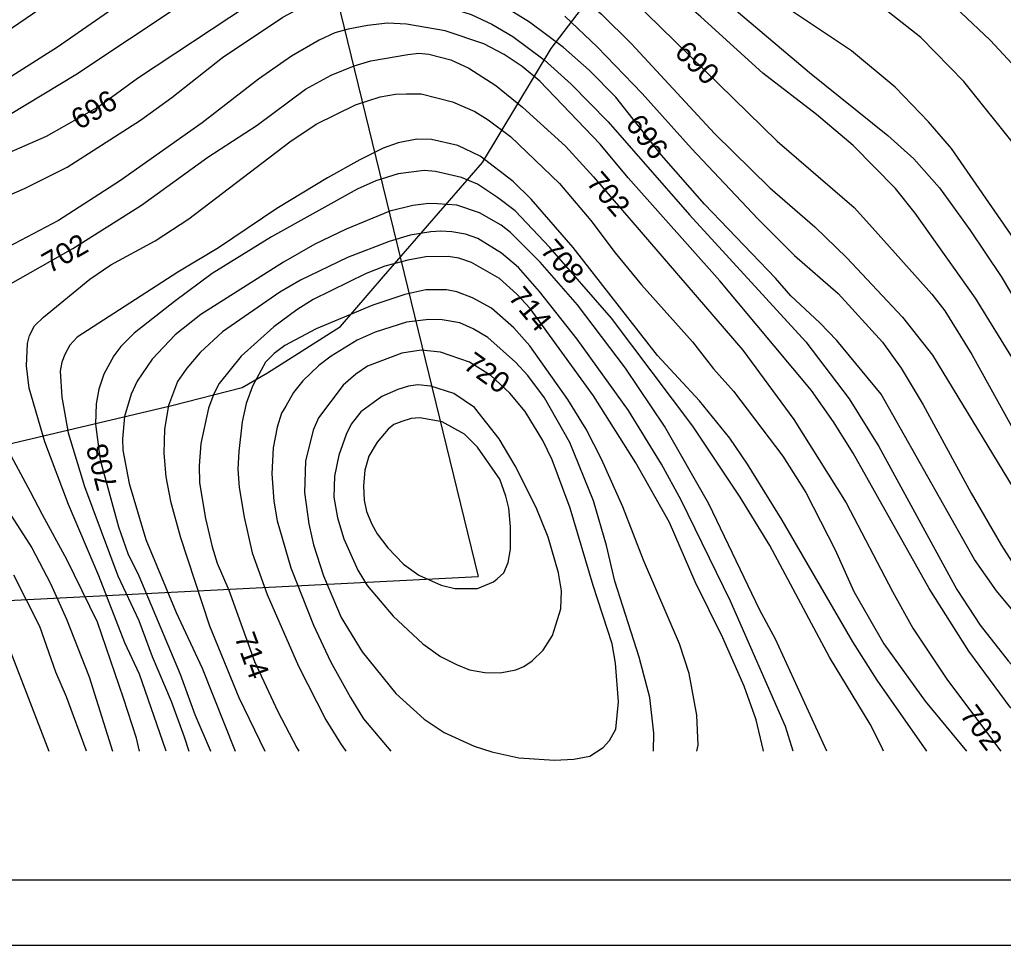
# Model space of a CAD drawing. Extents: x -709418 to -703832, y -1161719 to -1157826.
# Drawn here: x -706447 to -706070.4, y -1161718.9 to -1161364.7 of the extents above; entities that cross this region are included whole.
import ezdxf

# ---------------------------------------------------------------- set-up
doc = ezdxf.new("R2010")
doc.units = 0
for name, color, linetype in [('103_hranice KÚ', 7, 'Continuous'), ('120_vrstevnice hlavní', 7, 'Continuous'), ('121_vrstevnice hlavní_popis', 7, 'Continuous'), ('122_vrstevnice základní', 7, 'Continuous'), ('723_radioreléová trasa_UAP', 7, 'Continuous'), ('800_mřížka', 7, 'Continuous')]:
    doc.layers.add(name, color=color, linetype=linetype)

msp = doc.modelspace()

# ---------------------------------------------------------------- linework, layer by layer
at = {"layer": '103_hranice KÚ'}
msp.add_lwpolyline([(-706454.11, -1161527.78), (-706388.65, -1161512.35), (-706361.81, -1161505.4), (-706352.07, -1161499.85), (-706324.15, -1161482.08), (-706307.71, -1161462.97), (-706269.8, -1161419.34), (-706243.48, -1161375.76), (-706215.3, -1161338.76), (-706167.43, -1161298.96), (-706131.19, -1161259.29), (-706118.24, -1161260.88), (-706121.87, -1161224.74), (-706132.26, -1161199.29), (-706140.22, -1161183.53), (-706150.49, -1161170.73), (-706153.76, -1161155.91), (-706152.5, -1161152.34), (-706147.72, -1161124.93)], dxfattribs=at)
at = {"layer": '120_vrstevnice hlavní'}
for points in [[(-706303.48, -1161253.38), (-706295.5, -1161254.38), (-706277.14, -1161258.04), (-706268.43, -1161260.36), (-706252.47, -1161266.06), (-706224.54, -1161279.46), (-706184.64, -1161300.55), (-706144.74, -1161319.35), (-706124.8, -1161330.47), (-706104.42, -1161345.15), (-706075.35, -1161372.51), (-706050.41, -1161399.44)], [(-706455.1, -1161371.22), (-706431.59, -1161355.12), (-706410.5, -1161341.87), (-706388.7, -1161329.04), (-706369.6, -1161319.64), (-706346.8, -1161312.23), (-706324, -1161308.81), (-706314.88, -1161308.53), (-706302.34, -1161309.24), (-706286.39, -1161312.09), (-706266.44, -1161319.07), (-706254.47, -1161324.91), (-706246.49, -1161329.76), (-706234.52, -1161338.31), (-706212.72, -1161356.55), (-706157, -1161411.12), (-706127.5, -1161436.49), (-706120.5, -1161444.3), (-706097.72, -1161469.69), (-706092.73, -1161476.1), (-706082.47, -1161492.77), (-706061.81, -1161529.96)], [(-706224.71, -1161412.26), (-706247.77, -1161388.18), (-706254.61, -1161382.62), (-706261.45, -1161378.06), (-706269.29, -1161373.93), (-706284.1, -1161368.94), (-706298.92, -1161366.38), (-706306.11, -1161366.06), (-706313.74, -1161366.95), (-706321.15, -1161368.37), (-706326.33, -1161369.76), (-706332.27, -1161372.51), (-706342.95, -1161378.63), (-706355.49, -1161387.47), (-706377.15, -1161404.14), (-706408.79, -1161426.51), (-706432.16, -1161441.47), (-706453.96, -1161453.01)], [(-706052.39, -1161644.59), (-706054.26, -1161642.67), (-706067.8, -1161627.71), (-706083.61, -1161606.34), (-706098.72, -1161582.4), (-706127.79, -1161530.53), (-706135.34, -1161518.56), (-706143.75, -1161506.59), (-706178.94, -1161464.56), (-706214, -1161425.23), (-706224.71, -1161412.26)], [(-706137.94, -1161644.59), (-706157.57, -1161601.78), (-706163.56, -1161590.66), (-706183.08, -1161549.91), (-706200.03, -1161520.27), (-706214.99, -1161498.04), (-706233.38, -1161473.82), (-706247.63, -1161457.43), (-706259.03, -1161446.18), (-706262.59, -1161443.32), (-706270.85, -1161438.62), (-706279.55, -1161435.63), (-706286.96, -1161435.2), (-706290.34, -1161434.96), (-706296.45, -1161435.75), (-706305.22, -1161437.93), (-706322.01, -1161444.89), (-706333.98, -1161450.59), (-706345.95, -1161457.43), (-706377.58, -1161477.52), (-706387.41, -1161485.22), (-706396.25, -1161494.62), (-706401.95, -1161503.03), (-706404.23, -1161508.02), (-706406.79, -1161516.57), (-706407.65, -1161525.12), (-706407.51, -1161529.39), (-706405.08, -1161542.22)], [(-706293.22, -1161491.2), (-706300.63, -1161492.34), (-706313.73, -1161497.31), (-706318.3, -1161500.32), (-706323.15, -1161504.6), (-706332.55, -1161516.99), (-706334.55, -1161521.7), (-706337.54, -1161533.67), (-706337.97, -1161545.64), (-706336.26, -1161557.6), (-706334.41, -1161565.58), (-706330.7, -1161577.55), (-706323.86, -1161593.51), (-706315.88, -1161606.62), (-706302.91, -1161622.58), (-706292.08, -1161632.41), (-706284.39, -1161637.4), (-706272.99, -1161642.67), (-706266.15, -1161644.81), (-706255.89, -1161647.09), (-706242.21, -1161648.09), (-706234.8, -1161647.66), (-706228.67, -1161646.52), (-706223.54, -1161643.24), (-706221.12, -1161640.54), (-706218.7, -1161636.12), (-706217.7, -1161625.72), (-706218.84, -1161610.9), (-706220.12, -1161603.49), (-706227.39, -1161581.26), (-706236.23, -1161551.62), (-706243.07, -1161533.1), (-706246.63, -1161525.69), (-706253.47, -1161514.57), (-706259.31, -1161507.59), (-706266.58, -1161500.89), (-706274.7, -1161495.76), (-706285.82, -1161491.92), (-706293.22, -1161491.2)], [(-706457.09, -1161543.93), (-706442.27, -1161566.73), (-706435.15, -1161580.4), (-706429.02, -1161594.08), (-706420.41, -1161616.2), (-706411.36, -1161644.59)], [(-706405.08, -1161542.22), (-706398.67, -1161563.59), (-706386.99, -1161591.52), (-706377.15, -1161612.89), (-706364.47, -1161644.59)]]:
    msp.add_lwpolyline(points, dxfattribs=at)
at = {"layer": '122_vrstevnice základní'}
for points in [[(-706065.38, -1161413.4), (-706085.47, -1161388.32), (-706102, -1161371.51), (-706117.96, -1161358.82), (-706131.92, -1161348.57), (-706197.75, -1161306.53), (-706213.71, -1161297.13), (-706227.68, -1161289.72), (-706243.64, -1161282.31), (-706261.59, -1161275.47), (-706291.51, -1161268.48), (-706305.48, -1161266.2)], [(-706027.33, -1161504.88), (-706090.17, -1161413.97), (-706099, -1161403.71), (-706111.83, -1161390.46), (-706128.5, -1161376.64), (-706150.73, -1161361.82), (-706179.8, -1161339.87), (-706223.4, -1161308.67), (-706242.21, -1161296.41), (-706254.18, -1161289.57), (-706267.86, -1161283.45), (-706288.38, -1161278.03), (-706317.73, -1161274.47), (-706328.85, -1161274.04), (-706336.83, -1161274.47), (-706354.78, -1161277.03), (-706370.74, -1161281.31), (-706391.97, -1161288.43), (-706422.04, -1161302.11), (-706433.72, -1161306.25)], [(-706452.25, -1161335.46), (-706430.73, -1161324.91), (-706419.05, -1161318.07), (-706390.69, -1161303.4), (-706374.73, -1161296.13), (-706361.05, -1161291.85), (-706337.11, -1161287.58), (-706331.13, -1161287.01), (-706306.9, -1161287.58), (-706285.82, -1161290), (-706270.43, -1161294.13), (-706258.46, -1161299.12), (-706243.07, -1161307.53), (-706215.71, -1161326.2), (-706190.06, -1161346.43), (-706144.6, -1161384.9), (-706114.54, -1161408.98), (-706104.56, -1161417.96), (-706094.73, -1161429.07), (-706083.19, -1161445.04), (-706071.22, -1161462.99), (-706046.14, -1161504.88)], [(-706455.38, -1161389.46), (-706432.44, -1161375.07), (-706405.08, -1161355.98), (-706388.98, -1161345.72), (-706370.46, -1161335.17), (-706355.07, -1161328.62), (-706339.68, -1161323.34), (-706329.7, -1161321.06), (-706321.72, -1161319.93), (-706311.75, -1161319.35), (-706296.07, -1161321.06), (-706273.85, -1161327.48), (-706267.01, -1161330.33), (-706251.62, -1161339.87), (-706237.94, -1161350.42), (-706224.26, -1161362.53), (-706212.72, -1161373.93), (-706180.94, -1161408.27), (-706159.71, -1161429.07), (-706142.47, -1161443.9), (-706130.21, -1161455.86), (-706108.98, -1161478.52), (-706097.44, -1161493.06), (-706060.82, -1161553.33)], [(-706157.57, -1161463.56), (-706184.79, -1161435.34), (-706201.17, -1161416.54), (-706218.7, -1161394.31), (-706228.96, -1161384.05), (-706238.79, -1161375.35), (-706251.76, -1161365.67), (-706262.73, -1161358.82), (-706276.55, -1161351.99), (-706283.11, -1161349.56), (-706296.93, -1161345.86), (-706307.51, -1161344.12), (-706318.3, -1161344.15), (-706331.98, -1161346.14), (-706338.81, -1161348.24), (-706345.66, -1161351.27), (-706359.34, -1161359.11), (-706401.81, -1161387.18), (-706416.48, -1161397.87), (-706436.86, -1161409.41), (-706457.38, -1161418.25)], [(-706066.09, -1161495.48), (-706081.05, -1161471.25), (-706104.13, -1161438.77), (-706111.69, -1161429.22), (-706127.79, -1161412.83), (-706141.9, -1161401), (-706162.42, -1161385.19), (-706186.21, -1161363.53), (-706204.88, -1161347.43)], [(-706469.35, -1161439.76), (-706445.12, -1161429.22), (-706428.74, -1161421.1), (-706400.67, -1161403.14), (-706388.7, -1161394.45), (-706369.32, -1161379.2), (-706346.23, -1161363.67), (-706342.1, -1161361.53), (-706332.55, -1161357.97), (-706318.71, -1161354.86)], [(-706307.35, -1161354.74), (-706288.1, -1161358.26), (-706274.13, -1161362.67), (-706266.15, -1161366.38), (-706258.17, -1161371.08), (-706246.2, -1161380.06), (-706235.8, -1161389.32), (-706221.69, -1161403.71), (-706190.49, -1161439.33), (-706146.03, -1161487.93), (-706129.36, -1161509.73), (-706117.96, -1161527.97), (-706088.18, -1161582.68), (-706079.2, -1161596.36), (-706068.51, -1161610.04), (-706057.4, -1161622.16), (-706047.42, -1161631.84), (-706031.3, -1161644.59)], [(-706450.54, -1161400.86), (-706425.46, -1161385.61), (-706384.42, -1161358.4)], [(-706238.22, -1161363.39), (-706225.82, -1161375.07), (-706208.58, -1161392.88), (-706189.77, -1161413.97), (-706164.41, -1161440.9), (-706150.3, -1161454.87), (-706133.63, -1161469.4), (-706116.67, -1161488.07), (-706109.41, -1161498.04), (-706101, -1161512.01), (-706082.62, -1161545.92), (-706071.08, -1161565.87), (-706063.38, -1161577.84)], [(-706327.71, -1161385.9), (-706318.87, -1161382.34), (-706312.58, -1161380.44), (-706298.35, -1161378.06), (-706294.16, -1161377.53), (-706290.37, -1161377.92), (-706281.83, -1161380.06), (-706274.98, -1161383.19), (-706264.72, -1161389.89), (-706254.47, -1161398.15), (-706237.94, -1161413.12), (-706227.25, -1161424.8), (-706170.11, -1161491.2), (-706150.59, -1161517.71), (-706130.5, -1161549.63), (-706112.83, -1161583.54), (-706104.99, -1161597.5), (-706091.74, -1161617.45), (-706071.31, -1161644.59)], [(-706401.04, -1161644.59), (-706402.23, -1161639.68), (-706407.22, -1161624.29), (-706417.19, -1161595.22), (-706428.88, -1161571.29), (-706438.28, -1161554.19), (-706442.84, -1161545.35), (-706455.81, -1161521.41), (-706461.08, -1161509.44), (-706463.22, -1161502.6), (-706465.07, -1161492.34), (-706465.07, -1161483.79), (-706464.36, -1161480.37), (-706463.18, -1161476.99), (-706460.03, -1161472.54), (-706457.38, -1161470.4), (-706451.39, -1161466.27), (-706426.6, -1161452.3), (-706400.38, -1161435.63), (-706374.87, -1161417.25), (-706356.06, -1161404.99), (-706337.54, -1161391.31), (-706327.71, -1161385.9)], [(-706390.88, -1161644.59), (-706390.97, -1161644.24), (-706401.09, -1161615.17), (-706406.65, -1161603.2), (-706416.62, -1161577.55), (-706428.31, -1161550.2), (-706437.29, -1161526.26), (-706443.27, -1161505.74), (-706444.41, -1161497.19), (-706443.98, -1161488.64), (-706443.22, -1161485.52), (-706441.25, -1161481.83), (-706437.86, -1161478.52), (-706420.04, -1161463.99), (-706412.07, -1161458.43), (-706395.11, -1161449.31), (-706382.14, -1161440.9), (-706343.52, -1161411.41), (-706333.41, -1161404.71), (-706318.45, -1161397.3), (-706308.9, -1161394.16), (-706303.08, -1161393.2), (-706298.92, -1161393.02), (-706293.22, -1161393.02), (-706281.26, -1161396.16), (-706272.71, -1161399.86), (-706267.58, -1161403), (-706259.03, -1161409.41), (-706240.22, -1161427.37), (-706228.25, -1161441.47), (-706218.98, -1161453.87), (-706208.87, -1161466.12), (-706189.35, -1161487.93), (-706181.37, -1161498.33), (-706173.67, -1161506.88), (-706154.72, -1161531.67), (-706146.03, -1161545.64), (-706134.77, -1161567.58), (-706127.65, -1161583.54), (-706116.1, -1161603.49), (-706100.29, -1161625.43), (-706084.43, -1161644.59)], [(-706099.67, -1161644.59), (-706118.67, -1161617.45), (-706127.93, -1161602.78), (-706155.01, -1161556.18), (-706168.26, -1161534.81), (-706175.1, -1161524.83), (-706186.64, -1161510.58), (-706202.74, -1161493.2), (-706235.09, -1161451.88), (-706251.19, -1161433.35), (-706258.03, -1161426.65), (-706270.71, -1161416.96), (-706279.26, -1161412.83), (-706289.23, -1161410.55), (-706294.93, -1161410.41), (-706302.06, -1161411.83), (-706307.76, -1161413.83), (-706316.73, -1161418.28), (-706329.13, -1161425.23), (-706348.51, -1161436.91), (-706370.88, -1161452.02), (-706386.42, -1161461.28), (-706424.89, -1161486.22), (-706427.73, -1161489.22), (-706429.73, -1161492.77), (-706430.88, -1161495.71), (-706431.44, -1161499.18), (-706430.87, -1161509.16), (-706428.45, -1161522.84), (-706422.18, -1161543.36), (-706409.36, -1161577.55), (-706401.38, -1161594.65), (-706396.25, -1161608.33), (-706388.98, -1161625.43), (-706383.99, -1161639.11), (-706382.22, -1161644.59)], [(-706116.25, -1161644.59), (-706116.96, -1161642.82), (-706121.38, -1161634.27), (-706136.91, -1161608.62), (-706159.71, -1161565.87), (-706171.11, -1161547.35), (-706189.2, -1161520.27), (-706220.41, -1161478.95), (-706243.92, -1161451.88), (-706257.32, -1161437.77), (-706263.96, -1161432.67), (-706271.71, -1161427.65), (-706277.84, -1161425.09), (-706287.81, -1161422.81), (-706292.08, -1161422.38), (-706302.06, -1161423.66), (-706310.61, -1161426.37), (-706317.73, -1161429.5), (-706350.51, -1161447.74), (-706373.31, -1161461.85), (-706387.69, -1161472.54), (-706403.09, -1161484.65), (-706408.22, -1161489.78), (-706410.93, -1161493.34), (-706414.77, -1161500.32), (-706416.62, -1161506.02), (-706417.62, -1161511.72), (-706417.91, -1161519.42), (-706416.2, -1161533.1), (-706409.07, -1161558.75), (-706405.51, -1161569.01), (-706401.38, -1161577.55), (-706385.56, -1161615.17), (-706379.86, -1161630.56), (-706374.02, -1161644.24), (-706373.9, -1161644.59)], [(-706150.76, -1161644.59), (-706153.72, -1161635.12), (-706174.81, -1161587.24), (-706193.76, -1161548.49), (-706201.17, -1161534.81), (-706213.85, -1161514.29), (-706233.52, -1161486.93), (-706247.91, -1161468.69), (-706256.03, -1161459.57), (-706262.45, -1161454.01), (-706271.57, -1161448.46), (-706276.3, -1161446.8), (-706281.54, -1161445.89), (-706285.76, -1161445.66), (-706289.52, -1161445.89), (-706297.5, -1161447.17), (-706305.48, -1161449.59), (-706321.44, -1161455.72), (-706339.39, -1161464.41), (-706347.37, -1161468.97), (-706369.32, -1161484.08), (-706377.87, -1161492.06), (-706383, -1161498.04), (-706386.56, -1161503.17), (-706389.98, -1161512.29), (-706391.55, -1161521.41), (-706391.75, -1161530.61), (-706390.97, -1161539.65), (-706389.25, -1161548.95), (-706385.56, -1161562.45), (-706374.3, -1161596.65), (-706363.05, -1161624.01), (-706353.07, -1161644.59)], [(-706162.22, -1161644.59), (-706162.27, -1161643.96), (-706164.98, -1161632.56), (-706169.54, -1161619.73), (-706177.8, -1161601.21), (-706188.35, -1161579.83), (-706198.18, -1161557.04), (-706211.01, -1161534.24), (-706227.25, -1161508.59), (-706251.47, -1161475.24), (-706256.6, -1161469.69), (-706263.3, -1161463.7), (-706273.99, -1161457.57), (-706278.8, -1161455.97), (-706282.97, -1161455.29), (-706291.51, -1161455.44), (-706298.35, -1161456.74), (-706307.19, -1161459), (-706314.31, -1161461.85), (-706334.55, -1161471.82), (-706340.82, -1161475.67), (-706349.65, -1161482.23), (-706362.19, -1161493.48), (-706370.6, -1161503.88), (-706372.59, -1161507.81), (-706374.73, -1161513.29), (-706377.58, -1161526.83), (-706378.29, -1161535.38), (-706378.15, -1161541.93), (-706375.87, -1161555.61), (-706373.23, -1161566.39), (-706371.31, -1161572.71), (-706366.89, -1161582.97), (-706357.06, -1161610.33), (-706348.08, -1161629.42), (-706340.82, -1161643.39), (-706340.03, -1161644.59)], [(-706002.32, -1161644.59), (-706025.62, -1161628.28), (-706051.41, -1161607.33), (-706061.67, -1161596.93), (-706072.93, -1161583.25), (-706081.34, -1161571.29), (-706117.1, -1161508.02), (-706134.06, -1161487.5), (-706140.61, -1161480.66), (-706151.73, -1161470.4), (-706157.57, -1161463.56)], [(-706187.69, -1161644.59), (-706187.21, -1161642.25), (-706187.64, -1161630.85), (-706190.63, -1161614.89), (-706194.33, -1161603.49), (-706208.16, -1161571.57), (-706215.99, -1161551.05), (-706224.26, -1161532.81), (-706230.1, -1161521.41), (-706237.08, -1161510.01), (-706251.62, -1161489.49), (-706257.74, -1161482.65), (-706266.29, -1161475.1), (-706273.56, -1161471.11), (-706279.55, -1161468.83), (-706283.54, -1161468.12), (-706291.51, -1161468.12), (-706299.49, -1161469.83), (-706311.8, -1161473.94), (-706333.41, -1161482.94), (-706345.38, -1161489.35), (-706349.49, -1161492.4), (-706352.79, -1161495.76), (-706357.77, -1161504.88), (-706360.24, -1161511.5), (-706361.76, -1161518.56), (-706363.05, -1161529.96), (-706363.38, -1161536.72), (-706362.9, -1161543.64), (-706361.05, -1161555.04), (-706357.92, -1161568.72), (-706352.22, -1161584.68), (-706340.25, -1161612.04), (-706329.7, -1161632.56), (-706324.15, -1161641.68), (-706322.05, -1161644.59)], [(-706204.33, -1161644.59), (-706204.31, -1161644.53), (-706204.17, -1161637.69), (-706205.73, -1161624.01), (-706209.72, -1161608.62), (-706219.13, -1161579.55), (-706222.26, -1161565.87), (-706227.25, -1161548.77), (-706236.37, -1161526.54), (-706246.06, -1161509.44), (-706252.47, -1161500.89), (-706257.17, -1161495.76), (-706267.72, -1161486.36), (-706273.28, -1161482.94), (-706278.41, -1161480.66), (-706285.24, -1161479.52), (-706290.37, -1161479.38), (-706298.92, -1161480.37), (-706310.89, -1161484.22), (-706317.73, -1161487.35), (-706327.71, -1161493.48), (-706332.41, -1161497.05), (-706338.54, -1161502.89), (-706342.14, -1161507.3), (-706345.09, -1161512.58), (-706346.66, -1161515.28), (-706348.37, -1161520.56), (-706349.94, -1161528.54), (-706350.36, -1161538.51), (-706349.6, -1161548.95), (-706348.37, -1161556.47), (-706343.1, -1161574.42), (-706334.41, -1161596.36), (-706327.99, -1161610.33), (-706320.25, -1161624.08), (-706315.31, -1161632.27), (-706304.87, -1161644.59)], [(-706279.69, -1161611.48), (-706274.7, -1161613.46), (-706268.9, -1161614.56), (-706263.02, -1161614.6), (-706257.03, -1161613.46), (-706253.9, -1161612.18), (-706250.76, -1161610.04), (-706246.49, -1161605.91), (-706242.92, -1161600.35), (-706239.79, -1161590.09), (-706239.5, -1161583.25), (-706240.64, -1161576.42), (-706244.63, -1161562.74), (-706249.19, -1161551.34), (-706257.32, -1161535.38), (-706263.44, -1161525.12), (-706272.85, -1161513.15), (-706280.69, -1161507.73), (-706289.52, -1161504.88), (-706294.47, -1161504.37), (-706298.07, -1161504.88), (-706302.22, -1161506.15), (-706308.33, -1161508.87), (-706316.4, -1161514.81), (-706320.01, -1161519.42), (-706322.01, -1161523.41), (-706324.72, -1161531.39), (-706326.43, -1161539.37), (-706326.71, -1161547.35), (-706325.29, -1161555.32), (-706322.86, -1161563.31), (-706317.45, -1161575.28), (-706313.89, -1161581.26), (-706303.91, -1161592.94), (-706292.65, -1161603.49), (-706285.82, -1161608.33), (-706279.69, -1161611.48)], [(-706315.03, -1161548.49), (-706314.15, -1161552.89), (-706312.13, -1161557.69), (-706310.04, -1161561.45), (-706306.05, -1161566.73), (-706300.06, -1161573), (-706294.08, -1161577.27), (-706285.53, -1161581.12), (-706280.4, -1161582.4), (-706271.71, -1161582.4), (-706265.58, -1161579.76), (-706264.15, -1161578.67), (-706261.59, -1161576.42), (-706259.88, -1161572.43), (-706259.03, -1161567.3), (-706259.03, -1161558.75), (-706259.74, -1161551.62), (-706260.88, -1161547.06), (-706263.16, -1161540.51), (-706271.71, -1161528.25), (-706276.7, -1161523.26), (-706285.24, -1161518.56), (-706293.79, -1161516.99), (-706297.09, -1161517.36), (-706300.71, -1161518.48), (-706303.66, -1161519.65), (-706305.91, -1161521.41), (-706310.04, -1161526.4), (-706313.32, -1161531.67), (-706314.81, -1161537.1), (-706315.31, -1161543.07), (-706315.03, -1161548.49)], [(-706421.38, -1161644.59), (-706421.47, -1161644.24), (-706429.02, -1161623.86), (-706433.15, -1161614.32), (-706439.28, -1161596.93), (-706449.26, -1161577.27)], [(-706450.97, -1161605.2), (-706435.77, -1161644.59)]]:
    msp.add_lwpolyline(points, dxfattribs=at)
at = {"layer": '723_radioreléová trasa_UAP'}
for points in [[(-707182.2, -1157850.62), (-706271.36, -1161577.76)], [(-707518.88, -1161641.36), (-706271.36, -1161577.76)]]:
    msp.add_lwpolyline(points, dxfattribs=at)
at = {"layer": '800_mřížka'}
for points in [[(-703832.2, -1161718.9), (-703832.2, -1157825.62), (-709417.73, -1157825.62), (-709417.73, -1161718.9)], [(-703857.2, -1161693.9), (-703857.2, -1157850.62), (-709392.73, -1157850.62), (-709392.73, -1161693.9)]]:
    msp.add_lwpolyline(points, close=True, dxfattribs=at)

# ---------------------------------------------------------------- texts
at = {"layer": '121_vrstevnice hlavní_popis'}
for s, rotation, p in [('690', 315.4438, (-706196.68, -1161377.73)), ('696', 30.7079, (-706424.18, -1161407.08)), ('696', 307.8812, (-706215.36, -1161404.83)), ('702', 310.8855, (-706230.36, -1161427.22)), ('702', 29.5704, (-706435.51, -1161461.93)), ('708', 311.3077, (-706248.01, -1161453.16)), ('714', 309.9092, (-706260.2, -1161471.07)), ('720', 324.256, (-706277.57, -1161497.82)), ('708', 104.5981, (-706409.44, -1161543.55)), ('714', 290.1482, (-706364.84, -1161600.91)), ('702', 306.7219, (-706087.28, -1161630.77))]:
    msp.add_text(s, height=8, rotation=rotation, dxfattribs=at).set_placement(p)

doc.saveas('drawing.dxf')
